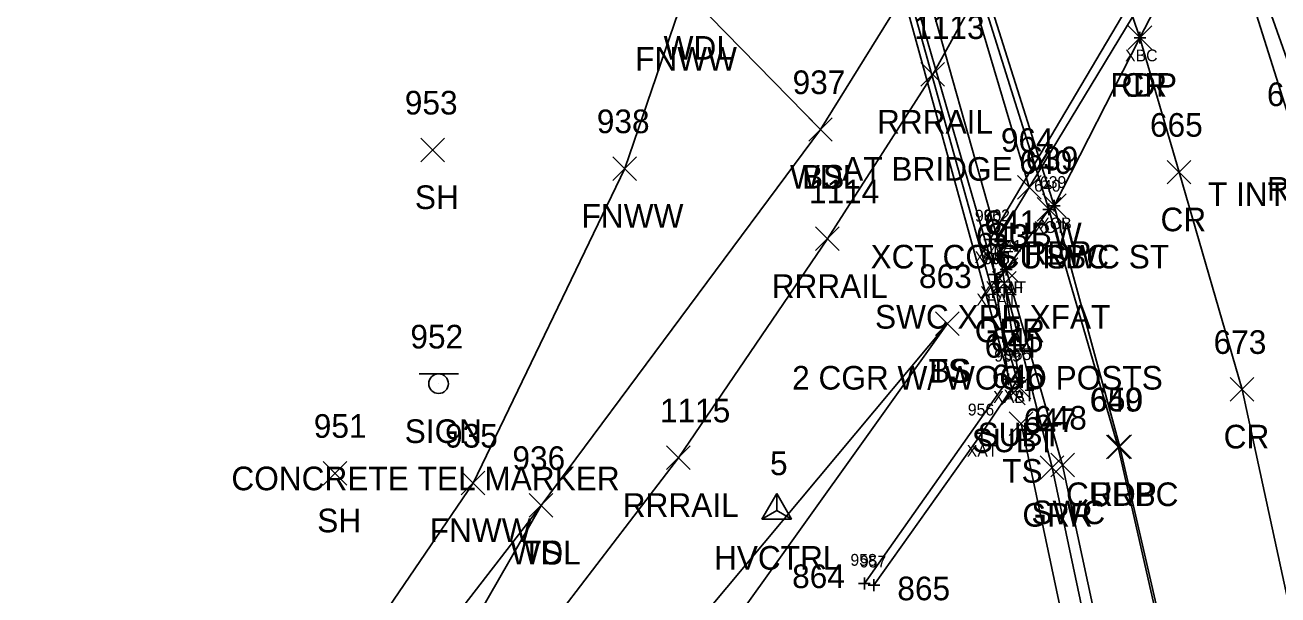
# Model space of a CAD drawing. Extents: x 1764889 to 1767296, y 695936 to 698960.
# Drawn here: x 1766244.6 to 1766350.6, y 696517.3 to 696565.6 of the extents above; entities that cross this region are included whole.
import ezdxf

# ---------------------------------------------------------------- set-up
doc = ezdxf.new("R2010")
doc.units = 0
for name, color, linetype in [('B_A', 7, 'Continuous'), ('B_I', 7, 'Continuous'), ('B_TIC', 7, 'Continuous'), ('BDC', 7, 'Continuous'), ('BELB', 7, 'Continuous'), ('BF', 7, 'Continuous'), ('BR', 7, 'Continuous'), ('BSUBM', 7, 'Continuous'), ('C_A', 7, 'Continuous'), ('C_I', 7, 'Continuous'), ('CPSM', 7, 'Continuous'), ('L_A', 7, 'Continuous'), ('L_I', 7, 'Continuous'), ('L_TIC', 7, 'Continuous'), ('LAWA', 7, 'Continuous'), ('LELB', 7, 'Continuous'), ('LFNC', 7, 'Continuous'), ('P_A', 7, 'Continuous'), ('P_I', 7, 'Continuous'), ('P_TIC', 7, 'Continuous'), ('PET', 7, 'Continuous'), ('PRC', 7, 'Continuous'), ('R_A', 7, 'Continuous'), ('R_C', 7, 'Continuous'), ('R_I', 7, 'Continuous'), ('R_TIC', 7, 'Continuous'), ('RC', 7, 'Continuous'), ('RGR', 7, 'Continuous'), ('RR', 7, 'Continuous'), ('RSW', 7, 'Continuous'), ('S_A', 7, 'Continuous'), ('S_C', 7, 'Continuous'), ('S_I', 7, 'Continuous'), ('SSGN', 7, 'Continuous'), ('U_A', 7, 'Continuous'), ('U_I', 7, 'Continuous'), ('U_TIC', 7, 'Continuous'), ('UT', 7, 'Continuous'), ('UW', 7, 'Continuous')]:
    doc.layers.add(name, color=color, linetype=linetype)

msp = doc.modelspace()

# ---------------------------------------------------------------- linework, layer by layer
at = {"layer": 'B_TIC'}
for p, q in [((1766338.91, 696564.49), (1766338.98, 696564.49)), ((1766331.65, 696550.27), (1766331.72, 696550.27)), ((1766331.2, 696549.96), (1766331.28, 696549.96)), ((1766326.19, 696547.42), (1766326.27, 696547.42)), ((1766326.88, 696547.45), (1766326.95, 696547.45)), ((1766327.59, 696544.87), (1766327.66, 696544.87)), ((1766327.59, 696544.87), (1766327.66, 696544.87)), ((1766326.62, 696544.45), (1766326.7, 696544.45)), ((1766326.82, 696543.82), (1766326.89, 696543.82)), ((1766327.77, 696535.58), (1766327.84, 696535.58)), ((1766328.67, 696535.71), (1766328.74, 696535.71)), ((1766328.67, 696535.71), (1766328.74, 696535.71)), ((1766325.55, 696531.02), (1766325.62, 696531.02)), ((1766315.6, 696518.3), (1766315.67, 696518.3)), ((1766316.4, 696518.16), (1766316.47, 696518.16))]:
    msp.add_line(p, q, dxfattribs=at)
for points in [[(1766338.9, 696563.99), (1766338.9, 696564.99)], [(1766338.4, 696564.49), (1766339.4, 696564.49)], [(1766331.15, 696550.27), (1766332.15, 696550.27)], [(1766331.2, 696549.46), (1766331.2, 696550.46)], [(1766331.65, 696549.77), (1766331.65, 696550.77)], [(1766330.7, 696549.96), (1766331.7, 696549.96)], [(1766326.19, 696546.92), (1766326.19, 696547.92)], [(1766326.88, 696546.95), (1766326.88, 696547.95)], [(1766325.69, 696547.42), (1766326.69, 696547.42)], [(1766326.38, 696547.45), (1766327.38, 696547.45)], [(1766326.62, 696543.95), (1766326.62, 696544.95)], [(1766327.08, 696544.87), (1766328.08, 696544.87)], [(1766327.08, 696544.87), (1766328.08, 696544.87)], [(1766327.58, 696544.37), (1766327.58, 696545.37)], [(1766327.58, 696544.37), (1766327.58, 696545.37)], [(1766326.12, 696544.45), (1766327.12, 696544.45)], [(1766326.31, 696543.82), (1766327.31, 696543.82)], [(1766326.81, 696543.32), (1766326.81, 696544.32)], [(1766327.27, 696535.58), (1766328.27, 696535.58)], [(1766327.77, 696535.08), (1766327.77, 696536.08)], [(1766328.16, 696535.71), (1766329.16, 696535.71)], [(1766328.16, 696535.71), (1766329.16, 696535.71)], [(1766328.66, 696535.21), (1766328.66, 696536.21)], [(1766328.66, 696535.21), (1766328.66, 696536.21)], [(1766325.04, 696531.02), (1766326.04, 696531.02)], [(1766325.54, 696530.52), (1766325.54, 696531.52)], [(1766315.09, 696518.3), (1766316.09, 696518.3)], [(1766315.59, 696517.8), (1766315.59, 696518.8)], [(1766316.4, 696517.66), (1766316.4, 696518.66)], [(1766315.9, 696518.16), (1766316.9, 696518.16)]]:
    msp.add_lwpolyline(points, dxfattribs=at)
at = {"layer": 'BDC'}
for points in [[(1766318.73, 696589.62), (1766331.2, 696549.96)], [(1766319.04, 696590.19), (1766331.65, 696550.27)]]:
    msp.add_lwpolyline(points, dxfattribs=at)
at = {"layer": 'BELB'}
msp.add_lwpolyline([(1766325.95, 696602.77), (1766338.9, 696564.49)], dxfattribs=at)
at = {"layer": 'BF'}
msp.add_lwpolyline([(1766315.05, 696584.59), (1766326.81, 696543.82), (1766327.58, 696544.87)], dxfattribs=at)
at = {"layer": 'BR'}
msp.add_lwpolyline([(1766315.3, 696584.59), (1766316.33, 696584.79), (1766327.58, 696544.87), (1766326.62, 696544.45)], dxfattribs=at)
at = {"layer": 'BSUBM'}
for points in [[(1766315.59, 696518.3), (1766327.77, 696535.58), (1766326.19, 696547.42), (1766344.21, 696577.89), (1766356.23, 696582.34), (1766357.05, 696579.35)], [(1766328.66, 696535.71), (1766326.88, 696547.45), (1766345.02, 696577.41), (1766349.94, 696579.26)], [(1766328.66, 696535.71), (1766325.54, 696531.02), (1766316.4, 696518.16)]]:
    msp.add_lwpolyline(points, dxfattribs=at)
at = {"layer": 'CPSM'}
for p, q in [((1766306.93, 696523.75), (1766308.18, 696525.91)), ((1766306.93, 696523.75), (1766308.18, 696525.91)), ((1766306.93, 696523.75), (1766308.18, 696525.91)), ((1766306.93, 696523.75), (1766308.18, 696525.91)), ((1766309.43, 696523.75), (1766308.18, 696525.91)), ((1766308.18, 696524.47), (1766308.18, 696525.91)), ((1766309.43, 696523.75), (1766308.18, 696525.91)), ((1766308.18, 696524.47), (1766308.18, 696525.91)), ((1766309.43, 696523.75), (1766308.18, 696525.91)), ((1766308.18, 696524.47), (1766308.18, 696525.91)), ((1766309.43, 696523.75), (1766308.18, 696525.91)), ((1766308.18, 696524.47), (1766308.18, 696525.91)), ((1766306.93, 696523.75), (1766308.18, 696524.47)), ((1766306.93, 696523.75), (1766308.18, 696524.47)), ((1766306.93, 696523.75), (1766308.18, 696524.47)), ((1766306.93, 696523.75), (1766308.18, 696524.47)), ((1766306.93, 696523.75), (1766309.43, 696523.75)), ((1766306.93, 696523.75), (1766309.43, 696523.75)), ((1766306.93, 696523.75), (1766309.43, 696523.75)), ((1766306.93, 696523.75), (1766309.43, 696523.75)), ((1766308.18, 696524.47), (1766308.18, 696524.47)), ((1766308.18, 696524.47), (1766309.43, 696523.75)), ((1766308.18, 696524.47), (1766308.18, 696524.47)), ((1766308.18, 696524.47), (1766309.43, 696523.75)), ((1766308.18, 696524.47), (1766308.18, 696524.47)), ((1766308.18, 696524.47), (1766309.43, 696523.75)), ((1766308.18, 696524.47), (1766308.18, 696524.47)), ((1766308.18, 696524.47), (1766309.43, 696523.75))]:
    msp.add_line(p, q, dxfattribs=at)
at = {"layer": 'L_TIC'}
for points in [[(1766310.88, 696555.72), (1766312.88, 696557.72)], [(1766312.88, 696555.72), (1766310.88, 696557.72)], [(1766310.88, 696555.72), (1766312.88, 696557.72)], [(1766312.88, 696555.72), (1766310.88, 696557.72)], [(1766278.08, 696553.99), (1766280.08, 696555.99)], [(1766280.08, 696553.99), (1766278.08, 696555.99)], [(1766294.32, 696552.41), (1766296.32, 696554.41)], [(1766296.32, 696552.41), (1766294.32, 696554.41)], [(1766321.62, 696539.3), (1766323.62, 696541.3)], [(1766323.62, 696539.3), (1766321.62, 696541.3)], [(1766321.62, 696539.3), (1766323.62, 696541.3)], [(1766323.62, 696539.3), (1766321.62, 696541.3)], [(1766327.84, 696530.83), (1766329.84, 696532.83)], [(1766329.84, 696530.83), (1766327.84, 696532.83)], [(1766269.82, 696526.63), (1766271.82, 696528.63)], [(1766271.82, 696526.63), (1766269.82, 696528.63)], [(1766281.49, 696525.8), (1766283.49, 696527.8)], [(1766283.49, 696525.8), (1766281.49, 696527.8)], [(1766287.24, 696523.91), (1766289.24, 696525.91)], [(1766289.24, 696523.91), (1766287.24, 696525.91)], [(1766287.24, 696523.91), (1766289.24, 696525.91)], [(1766289.24, 696523.91), (1766287.24, 696525.91)]]:
    msp.add_lwpolyline(points, dxfattribs=at)
at = {"layer": 'LAWA'}
msp.add_lwpolyline([(1766155.54, 696397.9), (1766161.77, 696405.44), (1766181.88, 696420.14), (1766196.06, 696430.7), (1766216.12, 696448.15), (1766224.84, 696455.16), (1766249.96, 696479.46), (1766272.12, 696504.03), (1766288.24, 696524.91), (1766311.88, 696556.72), (1766301.19, 696567.63)], dxfattribs=at)
at = {"layer": 'LELB'}
for points in [[(1766311.88, 696556.72), (1766333.81, 696592.11), (1766361.34, 696662.5)], [(1766158.91, 696379.33), (1766183.1, 696397.73), (1766210.95, 696420.2), (1766233.27, 696439.62), (1766253.97, 696460.11), (1766276.48, 696484.28), (1766294.63, 696506.78), (1766322.62, 696540.3)], [(1766256.38, 696458.71), (1766277.79, 696482.01), (1766297.06, 696504.51), (1766322.62, 696540.3)], [(1766328.84, 696531.83), (1766335.43, 696500.85), (1766336.09, 696495.53), (1766337.65, 696452.52), (1766334.4, 696430.54), (1766327.65, 696409.72), (1766321.65, 696385.78), (1766309.99, 696363.08), (1766304.82, 696352.13)], [(1766150.56, 696387.79), (1766167.12, 696399.48), (1766186.95, 696417.34), (1766197.67, 696430.72), (1766217.09, 696445.57), (1766224.84, 696455.16), (1766252.52, 696476.07), (1766275.69, 696502.98), (1766288.24, 696524.91)]]:
    msp.add_lwpolyline(points, dxfattribs=at)
at = {"layer": 'LFNC'}
msp.add_lwpolyline([(1766153.45, 696402.19), (1766162.21, 696408.4), (1766181.16, 696422.27), (1766195.92, 696435.85), (1766221.63, 696458.93), (1766246.19, 696483.05), (1766268.13, 696505.66), (1766282.49, 696526.8), (1766295.32, 696553.41), (1766299.86, 696566.71)], dxfattribs=at)
at = {"layer": 'P_TIC'}
for points in [[(1766337.9, 696563.49), (1766339.9, 696565.49)], [(1766339.9, 696563.49), (1766337.9, 696565.49)], [(1766337.9, 696563.49), (1766339.9, 696565.49)], [(1766339.9, 696563.49), (1766337.9, 696565.49)], [(1766341.21, 696552.11), (1766343.21, 696554.11)], [(1766343.21, 696552.11), (1766341.21, 696554.11)], [(1766330.65, 696549.27), (1766332.65, 696551.27)], [(1766332.65, 696549.27), (1766330.65, 696551.27)], [(1766330.65, 696549.27), (1766332.65, 696551.27)], [(1766332.65, 696549.27), (1766330.65, 696551.27)], [(1766346.54, 696533.73), (1766348.54, 696535.73)], [(1766348.54, 696533.73), (1766346.54, 696535.73)], [(1766336.19, 696528.87), (1766338.19, 696530.87)], [(1766338.19, 696528.87), (1766336.19, 696530.87)]]:
    msp.add_lwpolyline(points, dxfattribs=at)
at = {"layer": 'PET'}
for points in [[(1766331.65, 696550.27), (1766338.9, 696564.49), (1766345.39, 696577.08), (1766352.15, 696555.7), (1766356.95, 696538.79), (1766363.97, 696510.15), (1766367.19, 696487.5)], [(1766331.65, 696550.27), (1766337.19, 696529.87), (1766342.79, 696505.62), (1766343.93, 696497.35), (1766345.9, 696477.35), (1766345.61, 696451.13), (1766342.46, 696428.54), (1766337.12, 696406.59), (1766328.57, 696382.86), (1766317.54, 696359.04), (1766312, 696349.5), (1766322.36, 696346.4), (1766331.24, 696344.36), (1766343.78, 696364.8), (1766353.91, 696387.85), (1766362.68, 696417.29), (1766367.96, 696451.25), (1766367.19, 696487.5)]]:
    msp.add_lwpolyline(points, dxfattribs=at)
at = {"layer": 'PRC'}
msp.add_lwpolyline([(1766338.9, 696564.49), (1766342.21, 696553.11), (1766347.54, 696534.73), (1766353.36, 696507.93), (1766356.46, 696477.18), (1766356.12, 696449.17), (1766352.9, 696426.11), (1766347.27, 696403.75), (1766338.09, 696378.93), (1766326.54, 696354.51), (1766322.36, 696346.4)], dxfattribs=at)
at = {"layer": 'R_TIC'}
for points in [[(1766320.37, 696560.38), (1766322.37, 696562.38)], [(1766322.37, 696560.38), (1766320.37, 696562.38)], [(1766330.2, 696548.96), (1766332.2, 696550.96)], [(1766332.2, 696548.96), (1766330.2, 696550.96)], [(1766330.2, 696548.96), (1766332.2, 696550.96)], [(1766332.2, 696548.96), (1766330.2, 696550.96)], [(1766311.46, 696546.47), (1766313.46, 696548.47)], [(1766313.46, 696546.47), (1766311.46, 696548.47)], [(1766326.58, 696543.87), (1766328.58, 696545.87)], [(1766328.58, 696543.87), (1766326.58, 696545.87)], [(1766326.44, 696542.71), (1766328.44, 696544.71)], [(1766328.44, 696542.71), (1766326.44, 696544.71)], [(1766298.86, 696527.94), (1766300.86, 696529.94)], [(1766300.86, 696527.94), (1766298.86, 696529.94)], [(1766298.86, 696527.94), (1766300.86, 696529.94)], [(1766300.86, 696527.94), (1766298.86, 696529.94)], [(1766336.06, 696528.85), (1766338.06, 696530.85)], [(1766338.06, 696528.85), (1766336.06, 696530.85)], [(1766330.47, 696527.11), (1766332.47, 696529.11)], [(1766332.47, 696527.11), (1766330.47, 696529.11)], [(1766331.36, 696527.32), (1766333.36, 696529.32)], [(1766333.36, 696527.32), (1766331.36, 696529.32)]]:
    msp.add_lwpolyline(points, dxfattribs=at)
at = {"layer": 'RC'}
msp.add_lwpolyline([(1766331.2, 696549.96), (1766337.06, 696529.85), (1766342.58, 696505.51), (1766343.74, 696497.37), (1766345.77, 696477.42), (1766345.44, 696451.09), (1766342.29, 696428.54), (1766336.95, 696406.74), (1766328.54, 696383.01), (1766317.22, 696359.23), (1766311.75, 696349.59)], dxfattribs=at)
at = {"layer": 'RGR'}
for points in [[(1766346.64, 696575.95), (1766353.71, 696555.93), (1766359.06, 696540.35), (1766365.92, 696510.33), (1766368.76, 696487.08)], [(1766327.44, 696543.71), (1766331.47, 696528.11), (1766335.62, 696508.56), (1766335.43, 696500.85)]]:
    msp.add_lwpolyline(points, dxfattribs=at)
at = {"layer": 'RR'}
for points in [[(1766414.51, 696927.61), (1766410.63, 696876.83), (1766407.5, 696845.7), (1766404.42, 696820.76), (1766396.99, 696776.65), (1766388.17, 696735.44), (1766377.78, 696694.21), (1766366.7, 696658.73), (1766355.14, 696628.57), (1766340.23, 696595.43), (1766321.37, 696561.38), (1766312.46, 696547.47), (1766299.86, 696528.94)], [(1766299.86, 696528.94), (1766277.75, 696500.06), (1766257.52, 696477.14), (1766236.01, 696454.81), (1766202.65, 696425.22), (1766159.82, 696390.23), (1766109.4, 696350.61)]]:
    msp.add_lwpolyline(points, dxfattribs=at)
at = {"layer": 'RSW'}
msp.add_lwpolyline([(1766331.2, 696549.96), (1766327.58, 696544.87), (1766332.36, 696528.32), (1766337.43, 696504.73), (1766338.8, 696496.93), (1766340.76, 696477.25), (1766340.46, 696451.69), (1766337.58, 696429.77), (1766332.16, 696408.41), (1766323.74, 696384.6), (1766312.9, 696361.52), (1766306.49, 696349.77)], dxfattribs=at)
at = {"layer": 'SSGN'}
for p, q in [((1766277.93, 696536.05), (1766281.26, 696536.05)), ((1766279.57, 696535.21), (1766279.57, 696535.21))]:
    msp.add_line(p, q, dxfattribs=at)
msp.add_circle((1766279.57, 696535.21), 0.833, dxfattribs=at)
at = {"layer": 'U_TIC'}
for points in [[(1766328.54, 696550.83), (1766330.54, 696552.83)], [(1766330.54, 696550.83), (1766328.54, 696552.83)], [(1766327.18, 696533.41), (1766329.18, 696535.41)], [(1766329.18, 696533.41), (1766327.18, 696535.41)], [(1766327.68, 696533.92), (1766329.68, 696535.92)], [(1766329.68, 696533.92), (1766327.68, 696535.92)]]:
    msp.add_lwpolyline(points, dxfattribs=at)
at = {"layer": 'UT'}
for points in [[(1766314.63, 696585.18), (1766328.68, 696534.92)], [(1766314.28, 696584.9), (1766328.18, 696534.41)]]:
    msp.add_lwpolyline(points, dxfattribs=at)
at = {"layer": 'UW'}
msp.add_lwpolyline([(1766329.54, 696551.83), (1766318.78, 696588.01)], dxfattribs=at)

# ---------------------------------------------------------------- texts
at = {"layer": 'B_A'}
for s, p in [('XBC', (1766337.64, 696562.49)), ('XCT', (1766329.92, 696547.96)), ('XCB', (1766330.38, 696548.27)), ('XAB', (1766324.91, 696545.42)), ('XAT', (1766325.58, 696545.45)), ('XFAT', (1766325.84, 696542.87)), ('XRF', (1766326.34, 696542.87)), ('XFAT', (1766325.07, 696541.82)), ('XRF', (1766325.38, 696542.45)), ('XAB', (1766326.49, 696533.58)), ('XAT', (1766327.37, 696533.71)), ('XAT', (1766327.37, 696533.71)), ('XAT', (1766324.25, 696529.02))]:
    msp.add_text(s, height=1, dxfattribs=at).set_placement(p)
at = {"layer": 'B_I'}
for s, p in [('640', (1766329.95, 696551.46)), ('639', (1766330.44, 696551.77)), ('960', (1766324.94, 696548.92)), ('962', (1766325.67, 696548.95)), ('642', (1766325.41, 696545.95)), ('641', (1766326.66, 696546.37)), ('641', (1766326.66, 696546.37)), ('595', (1766325.63, 696545.32)), ('959', (1766326.58, 696537.08)), ('955', (1766327.48, 696537.21)), ('955', (1766327.48, 696537.21)), ('956', (1766324.34, 696532.52)), ('958', (1766314.41, 696519.8)), ('957', (1766315.21, 696519.66))]:
    msp.add_text(s, height=1, dxfattribs=at).set_placement(p)
at = {"layer": 'C_A'}
msp.add_text('HVCTRL', height=2, dxfattribs=at).set_placement((1766302.87, 696519.47))
msp.add_text('HVCTRL', height=2, dxfattribs=at).set_placement((1766302.87, 696519.47))
msp.add_text('HVCTRL', height=2, dxfattribs=at).set_placement((1766302.87, 696519.47))
msp.add_text('HVCTRL', height=2, dxfattribs=at).set_placement((1766302.87, 696519.47))
at = {"layer": 'C_I'}
msp.add_text('5', height=2, dxfattribs=at).set_placement((1766307.61, 696527.47))
msp.add_text('5', height=2, dxfattribs=at).set_placement((1766307.61, 696527.47))
msp.add_text('5', height=2, dxfattribs=at).set_placement((1766307.61, 696527.47))
msp.add_text('5', height=2, dxfattribs=at).set_placement((1766307.61, 696527.47))
at = {"layer": 'L_A'}
for s, p in [('WDL', (1766298.61, 696562.63)), ('FNWW', (1766296.2, 696561.71)), ('FNWW', (1766296.2, 696561.71)), ('WDL', (1766309.3, 696551.72)), ('BS', (1766310.32, 696551.72)), ('SH', (1766277.57, 696549.99)), ('FNWW', (1766291.67, 696548.41)), ('TS', (1766321.03, 696535.3)), ('BS', (1766321.06, 696535.3)), ('TS', (1766327.25, 696526.83)), ('SH', (1766269.31, 696522.63)), ('FNWW', (1766278.83, 696521.8)), ('WDL', (1766285.66, 696519.91)), ('TS', (1766286.65, 696519.91))]:
    msp.add_text(s, height=2, dxfattribs=at).set_placement(p)
at = {"layer": 'L_I'}
for s, p in [('937', (1766309.52, 696559.72)), ('937', (1766309.52, 696559.72)), ('953', (1766276.72, 696557.99)), ('938', (1766292.96, 696556.41)), ('863', (1766320.21, 696543.3)), ('863', (1766320.21, 696543.3)), ('646', (1766326.37, 696534.83)), ('951', (1766269.02, 696530.63)), ('935', (1766280.12, 696529.8)), ('936', (1766285.82, 696527.91)), ('936', (1766285.82, 696527.91)), ('864', (1766309.48, 696517.91)), ('865', (1766318.38, 696516.88))]:
    msp.add_text(s, height=2, dxfattribs=at).set_placement(p)
at = {"layer": 'P_A'}
for s, p in [('RDP', (1766336.39, 696559.49)), ('CR', (1766337.34, 696559.49)), ('RDP', (1766349.64, 696550.7)), ('CR', (1766340.64, 696548.11)), ('RDP', (1766329.13, 696545.27)), ('RDP', (1766329.13, 696545.27)), ('CR', (1766345.98, 696529.73)), ('RDP', (1766334.68, 696524.87))]:
    msp.add_text(s, height=2, dxfattribs=at).set_placement(p)
at = {"layer": 'P_I'}
for s, p in [('666', (1766349.64, 696558.7)), ('665', (1766339.75, 696556.11)), ('639', (1766329.23, 696553.27)), ('639', (1766329.23, 696553.27)), ('673', (1766345.13, 696537.73)), ('650', (1766334.7, 696532.87))]:
    msp.add_text(s, height=2, dxfattribs=at).set_placement(p)
at = {"layer": 'R_A'}
for s, p in [('RRRAIL', (1766316.66, 696556.38)), ('XCT CC ST SWC ST', (1766316.11, 696544.96)), ('CURBC', (1766326.78, 696544.96)), ('RRRAIL', (1766307.75, 696542.47)), ('SWC XRF XFAT', (1766316.49, 696539.87)), ('GRR', (1766324.93, 696538.71)), ('CURBC', (1766332.65, 696524.85)), ('RRRAIL', (1766295.15, 696523.94)), ('RRRAIL', (1766295.15, 696523.94)), ('GRR', (1766328.96, 696523.11)), ('SWC', (1766329.72, 696523.32))]:
    msp.add_text(s, height=2, dxfattribs=at).set_placement(p)
at = {"layer": 'R_C'}
for s, p in [('AT BRIDGE', (1766313.72, 696552.38)), ('2 CGR W/ WOOD POSTS', (1766309.48, 696534.71))]:
    msp.add_text(s, height=2, dxfattribs=at).set_placement(p)
at = {"layer": 'R_I'}
for s, p in [('1113', (1766319.81, 696564.38)), ('640', (1766328.7, 696552.96)), ('640', (1766328.7, 696552.96)), ('1114', (1766310.9, 696550.47)), ('641', (1766325.74, 696547.87)), ('643', (1766325.03, 696546.71)), ('649', (1766334.65, 696532.85)), ('1115', (1766298.3, 696531.94)), ('1115', (1766298.3, 696531.94)), ('647', (1766329.06, 696531.11)), ('648', (1766329.95, 696531.32))]:
    msp.add_text(s, height=2, dxfattribs=at).set_placement(p)
at = {"layer": 'S_A'}
msp.add_text('SIGN', height=2, dxfattribs=at).set_placement((1766276.71, 696530.19))
at = {"layer": 'S_C'}
for s, p in [('T INTERSECTION', (1766344.65, 696550.25)), ('CONCRETE TEL MARKER', (1766262.05, 696526.19))]:
    msp.add_text(s, height=2, dxfattribs=at).set_placement(p)
at = {"layer": 'S_I'}
msp.add_text('952', height=2, dxfattribs=at).set_placement((1766277.19, 696538.19))
at = {"layer": 'U_A'}
for s, p in [('SUBW', (1766325.95, 696546.83)), ('SUBT', (1766324.68, 696529.41)), ('SUBT', (1766325.17, 696529.92))]:
    msp.add_text(s, height=2, dxfattribs=at).set_placement(p)
at = {"layer": 'U_I'}
for s, p in [('964', (1766327.14, 696554.83)), ('644', (1766325.77, 696537.41)), ('645', (1766326.27, 696537.92))]:
    msp.add_text(s, height=2, dxfattribs=at).set_placement(p)

doc.saveas('drawing.dxf')
